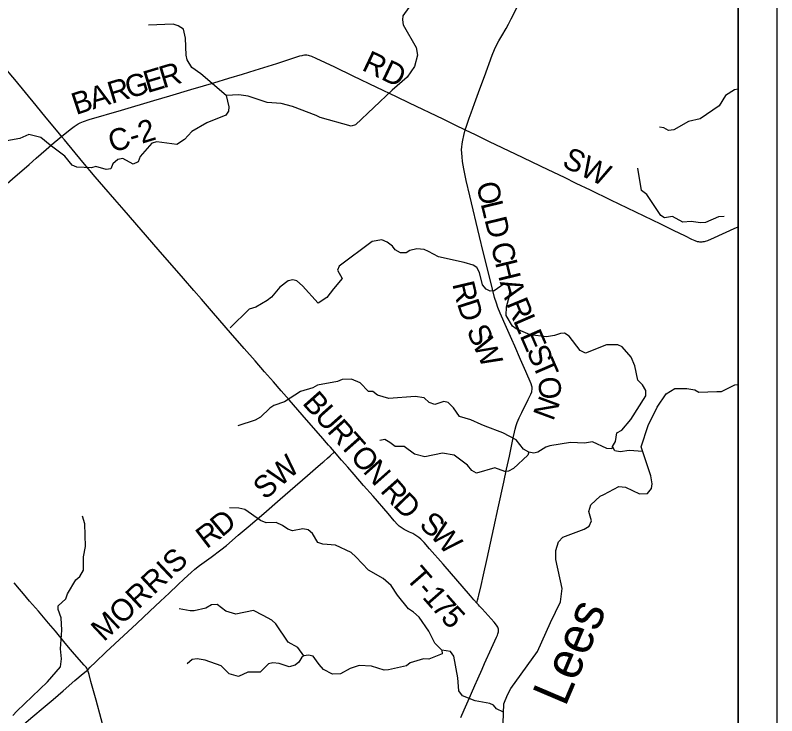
# Model space of a CAD drawing. Extents: x 0 to 34, y 0 to 22.
# Drawn here: x 7.032 to 9, y 16.287 to 18.098 of the extents above; entities that cross this region are included whole.
import ezdxf

# ---------------------------------------------------------------- set-up
doc = ezdxf.new("R2010")
doc.units = 0
for name, color, linetype in [('Default', 7, 'Continuous'), ('GM_X_County_Road', 7, 'Continuous'), ('GM_X_County_Road_Text', 7, 'Continuous'), ('GM_X_Minor_River', 7, 'Continuous'), ('GM_X_Minor_River_Text', 7, 'Continuous'), ('GM_X_Township_Road', 7, 'Continuous'), ('GM_X_Township_Road_Text', 7, 'Continuous'), ('SH_Cut_Line', 7, 'Continuous'), ('SH_Data', 7, 'Continuous')]:
    doc.layers.add(name, color=color, linetype=linetype)

msp = doc.modelspace()

# ---------------------------------------------------------------- linework, layer by layer
at = {"layer": 'Default'}
msp.add_lwpolyline([(8.9, 15.8067), (8.9, 19.2947), (8.3519, 19.0632), (7.2653, 18.6041), (6.6732, 18.3539), (6.6309, 18.3364), (6.5451, 17.2211), (6.5428, 17.1931), (6.4392, 15.8657), (6.5786, 15.8624), (7.3679, 15.8435), (8.1324, 15.8252)], close=True, dxfattribs=at)
at = {"layer": 'GM_X_County_Road'}
for points in [[(7.1522, 17.7843), (7.1477, 17.7899), (7.1124, 17.8328), (7.0863, 17.8644), (7.0586, 17.898), (7.0311, 17.9314), (6.9967, 17.972), (6.9634, 18.0116), (6.9288, 18.0526), (6.901, 18.0848), (6.8762, 18.1141), (6.8443, 18.1514)], [(7.1522, 17.7843), (7.1744, 17.8025), (7.1843, 17.81), (7.1894, 17.8135), (7.1948, 17.8166), (7.2003, 17.8194), (7.209, 17.8229), (7.2237, 17.8278), (7.307, 17.8526), (7.3904, 17.8772), (7.4321, 17.8896), (7.4857, 17.9057), (7.5184, 17.9154), (7.5453, 17.9231), (7.5839, 17.9348), (7.6196, 17.9457), (7.6523, 17.9556), (7.6967, 17.9697), (7.7085, 17.9733), (7.7263, 17.9789), (7.744, 17.9847), (7.7677, 17.9924), (7.7737, 17.9939), (7.7767, 17.9945), (7.7798, 17.9949), (7.7829, 17.9951), (7.786, 17.995), (7.7891, 17.9946), (7.7921, 17.9939), (7.798, 17.992), (7.8093, 17.9868), (7.857, 17.9642), (7.9046, 17.9414), (7.9661, 17.9117), (8.0165, 17.8875), (8.0502, 17.8715), (8.1369, 17.8295), (8.1703, 17.8132), (8.1928, 17.8026), (8.195, 17.8015)], [(8.195, 17.8015), (8.2208, 17.7891), (8.2571, 17.7715), (8.3243, 17.7392), (8.4083, 17.6988), (8.4503, 17.6788), (8.481, 17.6638), (8.5176, 17.6466), (8.5706, 17.6207), (8.6348, 17.5894), (8.6992, 17.5585), (8.7327, 17.5422), (8.7634, 17.5272), (8.7801, 17.5189), (8.7886, 17.5152), (8.7946, 17.5133), (8.7976, 17.5127), (8.8007, 17.5123), (8.8038, 17.5122), (8.8069, 17.5123), (8.81, 17.5126), (8.813, 17.5131), (8.816, 17.5139), (8.8219, 17.5159), (8.839, 17.5232), (8.8899, 17.5464), (8.9, 17.551)], [(7.8569, 16.969), (7.8466, 16.9816), (7.8418, 16.987), (7.8218, 17.0097), (7.7848, 17.0518), (7.7397, 17.1035), (7.7198, 17.1269), (7.6993, 17.1505), (7.6767, 17.1758), (7.652, 17.2045), (7.6237, 17.2367), (7.5888, 17.2767), (7.5443, 17.3279), (7.5135, 17.3639), (7.4937, 17.3867), (7.4669, 17.4177), (7.4016, 17.4926), (7.3141, 17.5935), (7.29, 17.6212), (7.2613, 17.6542), (7.2392, 17.6801), (7.2068, 17.718), (7.1593, 17.7753), (7.1522, 17.7843)], [(7.2199, 16.4064), (7.2263, 16.4128), (7.24, 16.4261), (7.2668, 16.4517), (7.2894, 16.4731), (7.3461, 16.5262), (7.3801, 16.558), (7.4074, 16.5834), (7.4301, 16.6046), (7.4527, 16.6259), (7.4685, 16.6409), (7.4866, 16.6578), (7.496, 16.6659), (7.5082, 16.6754), (7.5383, 16.6974), (7.5633, 16.7159), (7.5778, 16.7277), (7.6086, 16.7538), (7.6346, 16.7759), (7.6746, 16.8105), (7.7167, 16.8473), (7.7425, 16.8697), (7.7871, 16.9083), (7.8083, 16.9266), (7.8272, 16.9427), (7.8295, 16.9448), (7.839, 16.9528), (7.8461, 16.9591), (7.8569, 16.969)], [(7.3682, 15.843), (7.3678, 15.8535), (7.3674, 15.8566), (7.3657, 15.8658), (7.3612, 15.8839), (7.3542, 15.911), (7.3374, 15.974), (7.3234, 16.025), (7.3126, 16.0639), (7.3006, 16.1089), (7.2846, 16.1689), (7.2755, 16.2019), (7.2631, 16.2468), (7.2541, 16.2798), (7.2411, 16.3277), (7.2279, 16.3757), (7.2233, 16.3937), (7.221, 16.4018), (7.2199, 16.4064)]]:
    msp.add_lwpolyline(points, dxfattribs=at)
at = {"layer": 'GM_X_Minor_River'}
for points in [[(8.049, 18.1176), (8.034, 18.0957), (8.0328, 18.0855), (8.0345, 18.0726), (8.068, 18.0142), (8.072, 17.9944), (8.064, 17.9649), (8.0452, 17.9374), (8.0065, 17.9036), (7.9112, 17.8143), (7.9001, 17.8106), (7.82, 17.8331), (7.8102, 17.8381), (7.749, 17.8615), (7.7196, 17.8694), (7.6832, 17.872), (7.6345, 17.8881), (7.6099, 17.8921), (7.5769, 17.8902), (7.5123, 17.9458), (7.4886, 17.9624), (7.4763, 17.9826), (7.4738, 17.9944), (7.4723, 18.0384), (7.4673, 18.0613), (7.4537, 18.0705), (7.4401, 18.0744), (7.3764, 18.072)], [(8.9, 17.9063), (8.8906, 17.9052), (8.8673, 17.8899), (8.8511, 17.8631), (8.8018, 17.8295), (8.7722, 17.8234), (8.7344, 17.8014), (8.72, 17.8), (8.7083, 17.8069), (8.697, 17.8086)], [(7.5769, 17.8902), (7.5845, 17.8609), (7.5836, 17.8499), (7.5767, 17.8393), (7.5272, 17.8197), (7.4883, 17.7974), (7.4695, 17.7767), (7.4496, 17.7636), (7.3985, 17.7706), (7.3852, 17.7673), (7.3549, 17.7327), (7.3498, 17.7187), (7.3369, 17.7128), (7.3101, 17.7275), (7.2972, 17.7249), (7.2846, 17.7133), (7.2795, 17.7005), (7.267, 17.6991), (7.2409, 17.7069), (7.2291, 17.7032), (7.1916, 17.7048), (7.1792, 17.7102), (7.1608, 17.7331), (7.1229, 17.762), (7.0981, 17.782), (7.0674, 17.7891), (7.0442, 17.7791), (7.0104, 17.7734)], [(8.864, 17.5777), (8.8495, 17.5767), (8.816, 17.5623), (8.8027, 17.5609), (8.7785, 17.5646), (8.7572, 17.5625), (8.7308, 17.5776), (8.7103, 17.5744), (8.7005, 17.5801), (8.6644, 17.6344), (8.6508, 17.6451), (8.6412, 17.7025)], [(8.6535, 16.9706), (8.6182, 16.9732), (8.5954, 16.9696), (8.5817, 16.9717), (8.5758, 16.9831), (8.5835, 16.9959), (8.5868, 17.0187), (8.5994, 17.025), (8.6228, 17.0532), (8.6618, 17.1139), (8.6619, 17.1279), (8.653, 17.1424), (8.6406, 17.1543), (8.6334, 17.192), (8.6238, 17.2144), (8.6002, 17.2409), (8.5893, 17.2459), (8.5601, 17.2462), (8.5056, 17.2244), (8.4917, 17.231), (8.4633, 17.2684), (8.4512, 17.2758), (8.4414, 17.2755), (8.4254, 17.2696), (8.4053, 17.2667), (8.3625, 17.2721), (8.327, 17.2869), (8.3172, 17.2938), (8.3012, 17.3213), (8.3018, 17.3441), (8.309, 17.3728), (8.3106, 17.3853), (8.3092, 17.3967), (8.296, 17.4037), (8.2701, 17.3854), (8.2598, 17.3843), (8.2493, 17.3894), (8.2399, 17.4008), (8.2323, 17.4328), (8.2252, 17.4458), (8.2154, 17.4519), (8.192, 17.4586), (8.1262, 17.4733), (8.1002, 17.4872), (8.0893, 17.4919), (8.0696, 17.4936), (8.0521, 17.4896), (8.0425, 17.4837), (8.0278, 17.4834), (8.0142, 17.4915), (8.0075, 17.5011), (7.9936, 17.5111), (7.9796, 17.5169), (7.9549, 17.5126), (7.8697, 17.449), (7.8654, 17.4392), (7.8769, 17.417), (7.855, 17.3903), (7.8373, 17.3685), (7.8148, 17.3532), (7.7747, 17.398), (7.7597, 17.411), (7.7499, 17.4142), (7.7373, 17.4113), (7.7163, 17.3952), (7.6948, 17.3688), (7.683, 17.3602), (7.6544, 17.3434), (7.6369, 17.3379), (7.5878, 17.2895)], [(8.5758, 16.9831), (8.5735, 16.9775), (8.561, 16.9783), (8.524, 16.995), (8.5031, 16.9915), (8.4671, 16.9937), (8.414, 16.9848), (8.4033, 16.9818), (8.3823, 16.9688), (8.3724, 16.9662), (8.3592, 16.9686), (8.346, 16.976), (8.3269, 17.0008), (8.2926, 17.0183), (8.2469, 17.0354), (8.2364, 17.0397), (8.2096, 17.0517), (8.1805, 17.0604), (8.1648, 17.0833), (8.1509, 17.0967), (8.1396, 17.0995), (8.1168, 17.0917), (8.1017, 17.0972), (8.0889, 17.1087), (8.0658, 17.1124), (7.9979, 17.1074), (7.968, 17.116), (7.956, 17.1249), (7.945, 17.1257), (7.9233, 17.148), (7.901, 17.1569), (7.8771, 17.156), (7.8646, 17.1512), (7.8133, 17.1419), (7.8011, 17.1344), (7.7695, 17.1256), (7.7283, 17.0983), (7.7001, 17.0895), (7.6898, 17.082), (7.6661, 17.0591), (7.6523, 17.0513), (7.6078, 17.037)], [(8.2928, 16.2682), (8.2945, 16.3183), (8.3046, 16.3417), (8.3131, 16.3579), (8.382, 16.4532), (8.4151, 16.528), (8.441, 16.5816), (8.4452, 16.6165), (8.4294, 16.6914), (8.4292, 16.7141), (8.4359, 16.7372), (8.4474, 16.7492), (8.5022, 16.7695), (8.5156, 16.7774), (8.521, 16.791), (8.5145, 16.8153), (8.52, 16.8323), (8.5437, 16.8545), (8.5532, 16.8589), (8.5921, 16.8798), (8.6095, 16.8777), (8.6454, 16.861), (8.6662, 16.8619), (8.6762, 16.8751), (8.6783, 16.8865), (8.6743, 16.9078), (8.6497, 16.9824), (8.6674, 17.0372), (8.691, 17.0851), (8.7138, 17.1191), (8.7363, 17.1329), (8.7677, 17.1329), (8.7882, 17.1297), (8.7983, 17.1239), (8.845, 17.1249), (8.8575, 17.1256), (8.8918, 17.1423), (8.9, 17.1436)], [(8.3592, 16.9686), (8.3565, 16.9611), (8.3201, 16.9265), (8.3071, 16.9191), (8.2976, 16.9188), (8.2716, 16.9278), (8.2244, 16.9142), (8.2123, 16.9208), (8.2007, 16.9346), (8.1665, 16.9607), (8.1363, 16.966), (8.0903, 16.9562), (8.0642, 16.9633), (8.0375, 16.9833), (8.014, 16.9835), (8.0005, 16.9939), (7.9869, 17.0009), (7.9747, 16.9983)], [(8.294, 16.2971), (8.2754, 16.3056), (8.2683, 16.3151), (8.2585, 16.3194), (8.2211, 16.3258), (8.1882, 16.3387), (8.1785, 16.3517), (8.1758, 16.3851), (8.1655, 16.4417), (8.1569, 16.4536), (8.1345, 16.4569), (8.1165, 16.4752), (8.1013, 16.5058), (8.0756, 16.5424), (8.0617, 16.5551), (8.0485, 16.564), (8.0197, 16.5991), (8.004, 16.6243), (7.9834, 16.6424), (7.9449, 16.6633), (7.9127, 16.6981), (7.9003, 16.7089), (7.8596, 16.7279), (7.827, 16.7309), (7.8142, 16.7348), (7.8008, 16.7581), (7.7891, 16.768), (7.7751, 16.7701), (7.7489, 16.7654), (7.7365, 16.7697), (7.7233, 16.7793), (7.7063, 16.7871), (7.6805, 16.7862), (7.6662, 16.7917), (7.6256, 16.8202), (7.6104, 16.8241), (7.5858, 16.8251)], [(7.0265, 16.2879), (7.0361, 16.2996), (7.1158, 16.375), (7.1492, 16.4137), (7.1521, 16.4346), (7.1489, 16.46), (7.1529, 16.5089), (7.1506, 16.5401), (7.1432, 16.5618), (7.1433, 16.5716), (7.1632, 16.5896), (7.1675, 16.6025), (7.1888, 16.6387), (7.1995, 16.6477), (7.2088, 16.6639), (7.2084, 16.6981), (7.214, 16.7246), (7.212, 16.7834), (7.2065, 16.8035)], [(8.1345, 16.4569), (8.1352, 16.4474), (8.1013, 16.434), (8.0873, 16.4349), (8.053, 16.4239), (8.0435, 16.4168), (7.9971, 16.4059), (7.9854, 16.4056), (7.9525, 16.4154), (7.9207, 16.4173), (7.8978, 16.4092), (7.8731, 16.3958), (7.8522, 16.3952), (7.8288, 16.4068), (7.818, 16.4198), (7.8109, 16.4294), (7.8019, 16.4416), (7.7898, 16.4437), (7.7776, 16.4419), (7.7627, 16.4637), (7.7375, 16.4776), (7.7058, 16.5253), (7.6956, 16.5345), (7.673, 16.5461), (7.6478, 16.5597), (7.6022, 16.5499), (7.5765, 16.5577), (7.5539, 16.5747), (7.5395, 16.5744), (7.5246, 16.5658), (7.4946, 16.5586), (7.484, 16.5583), (7.4556, 16.5635)], [(7.7776, 16.4419), (7.7727, 16.4385), (7.7653, 16.4257), (7.7554, 16.4182), (7.7398, 16.4142), (7.7141, 16.4224), (7.6982, 16.4241), (7.6868, 16.4216), (7.6654, 16.4005), (7.6335, 16.4001), (7.6088, 16.389), (7.5849, 16.3956), (7.5643, 16.4167), (7.5232, 16.4312), (7.502, 16.4344), (7.4891, 16.4327), (7.4764, 16.4218)]]:
    msp.add_lwpolyline(points, dxfattribs=at)
at = {"layer": 'GM_X_Township_Road'}
for points in [[(8.195, 17.8015), (8.1979, 17.811), (8.2054, 17.8314), (8.2107, 17.8457), (8.2192, 17.8691), (8.2331, 17.907), (8.2449, 17.9391), (8.265, 17.9946), (8.2706, 18.0091), (8.2757, 18.0204), (8.2815, 18.0314), (8.2894, 18.0447), (8.3006, 18.0634), (8.3067, 18.0742), (8.3138, 18.088), (8.3337, 18.1267)], [(8.2251, 16.5787), (8.2261, 16.5828), (8.227, 16.5864), (8.2285, 16.5924), (8.23, 16.5987), (8.2363, 16.624), (8.2421, 16.6513), (8.2514, 16.6938), (8.2687, 16.7727), (8.28, 16.8243), (8.2945, 16.8911), (8.3019, 16.9245), (8.3092, 16.9579), (8.3184, 17.0013), (8.3241, 17.0281), (8.3263, 17.0374), (8.3289, 17.0455), (8.3345, 17.057), (8.3411, 17.0711), (8.3576, 17.1045), (8.3645, 17.1185), (8.3667, 17.1243), (8.3675, 17.1273), (8.3679, 17.1303), (8.368, 17.1334), (8.3676, 17.1365), (8.367, 17.1395), (8.3651, 17.1454), (8.3516, 17.1769), (8.338, 17.2082), (8.3233, 17.2425), (8.3157, 17.2595), (8.3018, 17.2907), (8.2854, 17.3277), (8.2795, 17.342), (8.2754, 17.3537), (8.271, 17.3686), (8.2656, 17.3897), (8.2545, 17.435), (8.2418, 17.4862), (8.2323, 17.5255), (8.2068, 17.6312), (8.1978, 17.6706), (8.1916, 17.701), (8.1883, 17.7194), (8.1867, 17.7317), (8.1859, 17.741), (8.1857, 17.7503), (8.186, 17.7565), (8.187, 17.7657), (8.1886, 17.7749), (8.1912, 17.7871), (8.195, 17.8015)], [(6.5453, 17.2206), (6.619, 17.2923), (6.6564, 17.3296), (6.6914, 17.3648), (6.7221, 17.3956), (6.766, 17.4396), (6.7834, 17.4572), (6.8206, 17.4947), (6.8407, 17.5141), (6.859, 17.5309), (6.8847, 17.5534), (6.9224, 17.5858), (6.9458, 17.6061), (6.9763, 17.6326), (7.0256, 17.6752), (7.0679, 17.7118), (7.0866, 17.7281), (7.1123, 17.7505), (7.1333, 17.7689), (7.1428, 17.7769), (7.1477, 17.7808), (7.1522, 17.7843)], [(8.2251, 16.5787), (8.2174, 16.5871), (8.2087, 16.5971), (8.1379, 16.6792), (8.103, 16.7188), (8.0885, 16.735), (8.0799, 16.744), (8.0753, 16.7482), (8.0704, 16.7519), (8.0652, 16.7552), (8.0597, 16.7581), (8.0512, 16.7621), (8.0372, 16.7687), (8.0318, 16.7718), (8.0268, 16.7754), (8.0244, 16.7774), (8.0199, 16.7817), (8.0116, 16.7909), (7.9955, 16.8098), (7.9569, 16.8545), (7.9325, 16.8826), (7.908, 16.9108), (7.8918, 16.9296), (7.8755, 16.9483), (7.8569, 16.969)], [(7.2199, 16.4064), (7.2155, 16.4126), (7.2106, 16.4181), (7.1858, 16.4463), (7.1696, 16.465), (7.1578, 16.479), (7.1361, 16.5059), (7.1184, 16.5271), (7.092, 16.5579), (7.0696, 16.5836), (7.0536, 16.6026), (7.0435, 16.6146), (7.0296, 16.6313)], [(8.1837, 16.283), (8.1925, 16.3029), (8.2024, 16.3256), (8.2111, 16.3455), (8.2197, 16.3655), (8.2272, 16.3826), (8.2384, 16.4081), (8.2448, 16.4223), (8.2627, 16.4619), (8.2757, 16.4901), (8.2783, 16.4958), (8.2795, 16.4987), (8.2804, 16.5017), (8.281, 16.5047), (8.2812, 16.5078), (8.2808, 16.5108), (8.2801, 16.5138), (8.2789, 16.5166), (8.2774, 16.5193), (8.2757, 16.5219), (8.2696, 16.5291), (8.2384, 16.5637), (8.2322, 16.5706), (8.2294, 16.5738), (8.2251, 16.5787)], [(7.0258, 16.2416), (7.0544, 16.2655), (7.0781, 16.2854), (7.1042, 16.3075), (7.1303, 16.3297), (7.1562, 16.3518), (7.1866, 16.3785), (7.2079, 16.3962), (7.2152, 16.4024), (7.2199, 16.4064)]]:
    msp.add_lwpolyline(points, dxfattribs=at)
at = {"layer": 'SH_Cut_Line'}
msp.add_lwpolyline([(6.6654, 18.7733), (6.6363, 18.3979), (6.6309, 18.3364), (6.5451, 17.2211), (6.5428, 17.1931), (6.4392, 15.8657), (6.5786, 15.8624), (7.3679, 15.8435), (8.1324, 15.8252), (8.9, 15.8067), (8.9, 20.9), (6.8302, 20.9), (6.6949, 19.1537), (6.6858, 19.0362)], dxfattribs=at)
at = {"layer": 'SH_Data'}
for p, q in [((9, 21), (9, 14)), ((8.9, 20.9), (8.9, 14.1))]:
    msp.add_line(p, q, dxfattribs=at)

# ---------------------------------------------------------------- texts
at = {"layer": 'GM_X_County_Road_Text'}
for s, height, rotation, p in [('RD', 0.05682, 334.6539, (7.9252, 17.9568)), ('R', 0.0568, 16.7142, (7.4144, 17.9083)), ('G', 0.0568, 16.7142, (7.3258, 17.8817)), ('E', 0.0568, 16.7148, (7.3737, 17.8961)), ('R', 0.0568, 16.7142, (7.2811, 17.8683)), ('B', 0.0568, 18.2905, (7.1893, 17.8393)), ('A', 0.0568, 16.7505, (7.2333, 17.8539)), ('C-2', 0.05682, 16.8314, (7.2826, 17.7421)), ('SW', 0.05682, 334.0386, (8.4422, 17.7083)), ('SW', 0.05682, 40.8009, (7.6777, 16.8435)), ('D', 0.0568, 39.8157, (7.566, 16.7471)), ('R', 0.0568, 37.2547, (7.5267, 16.7172)), ('MORRIS', 0.05682, 43.2375, (7.2612, 16.4771))]:
    msp.add_text(s, height=height, rotation=rotation, dxfattribs=at).set_placement(p)
at = {"layer": 'GM_X_Minor_River_Text'}
msp.add_text('Lees', height=0.0947, rotation=66.9733, dxfattribs=at).set_placement((8.4535, 16.3086))
at = {"layer": 'GM_X_Township_Road_Text'}
for s, rotation, p in [('O', 282.3644, (8.2235, 17.6613)), ('L', 283.6388, (8.2345, 17.6111)), ('D', 283.6929, (8.2446, 17.5698)), ('C', 283.6926, (8.2605, 17.5042)), ('H', 283.7357, (8.2716, 17.4588)), ('R', 283.3111, (8.1612, 17.4034)), ('A', 285.6925, (8.284, 17.4082)), ('D', 287.8856, (8.1732, 17.3532)), ('R', 292.3731, (8.2999, 17.3532)), ('L', 293.5042, (8.3181, 17.3089)), ('S', 293.5142, (8.1975, 17.2838)), ('E', 293.5454, (8.3351, 17.2699)), ('W', 293.9801, (8.213, 17.2482)), ('S', 293.5442, (8.3521, 17.231)), ('T', 293.4068, (8.3674, 17.1958)), ('O', 274.613, (8.3831, 17.1616)), ('B', 311.5979, (7.772, 17.0944)), ('N', 249.7539, (8.388, 17.1182)), ('U', 311.5992, (7.803, 17.0595)), ('R', 311.5979, (7.8362, 17.0221)), ('T', 311.598, (7.8672, 16.9872)), ('O', 311.5992, (7.8954, 16.9554)), ('N', 311.5978, (7.9286, 16.9181)), ('R', 311.5997, (7.9734, 16.8676)), ('D', 314.2132, (8.0063, 16.8306)), ('S', 320.4883, (8.0734, 16.7763)), ('W', 311.9506, (8.1014, 16.7535)), ('T', 311.062, (8.0388, 16.6427)), ('-', 311.0829, (8.0667, 16.6106)), ('1', 311.1441, (8.0821, 16.593)), ('7', 311.3827, (8.1053, 16.5664)), ('5', 312.3919, (8.1292, 16.5393))]:
    msp.add_text(s, height=0.0568, rotation=rotation, dxfattribs=at).set_placement(p)

doc.saveas('drawing.dxf')
